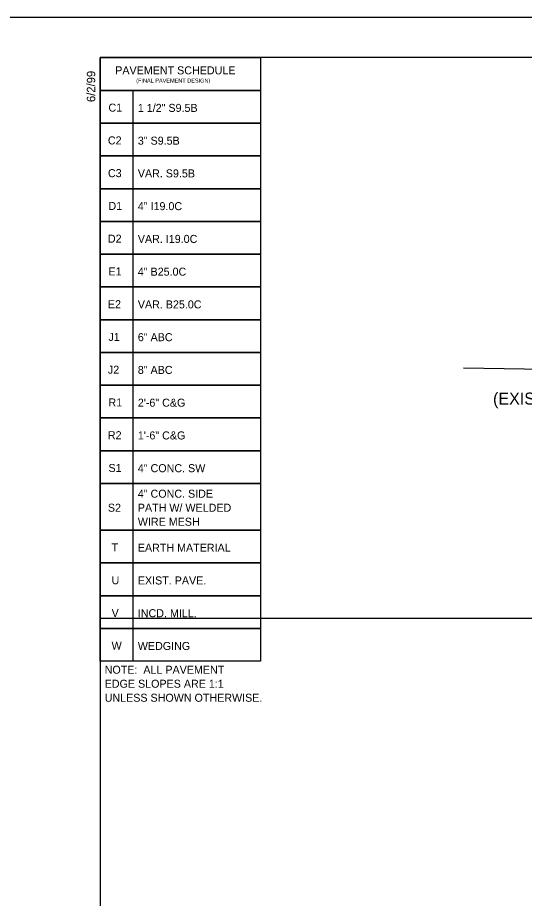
# Model space of a CAD drawing. Extents: x 1487909 to 1489267, y 497866 to 499814.
# Drawn here: x 1488894.8 to 1488926.4, y 498162.1 to 498217.1 of the extents above; entities that cross this region are included whole.
import ezdxf

# ---------------------------------------------------------------- set-up
doc = ezdxf.new("R2010")
doc.units = 0
for name, color, linetype in [('Prop Pavement Schedule Description CELL', 7, 'Continuous'), ('Scratch_Level_1', 7, 'Continuous'), ('Sheet Plot Border Outside CELL', 7, 'Continuous'), ('Sheet Typical CELL', 7, 'Continuous'), ('Typical Hinge Slope Arterial CELL', 7, 'Continuous'), ('Typical Pavement Slope CELL', 7, 'Continuous')]:
    doc.layers.add(name, color=color, linetype=linetype)

msp = doc.modelspace()

# ---------------------------------------------------------------- linework, layer by layer
at = {"layer": 'Prop Pavement Schedule Description CELL'}
for points in [[(1488902.009, 498212.542), (1488899.964, 498212.542), (1488899.964, 498214.587), (1488909.964, 498214.587), (1488909.964, 498212.542), (1488902.009, 498212.542)], [(1488902.009, 498210.496), (1488899.964, 498210.496), (1488899.964, 498212.542), (1488909.964, 498212.542), (1488909.964, 498210.496), (1488902.009, 498210.496), (1488902.009, 498212.542)], [(1488902.009, 498208.451), (1488899.964, 498208.451), (1488899.964, 498210.496), (1488909.964, 498210.496), (1488909.964, 498208.451), (1488902.009, 498208.451), (1488902.009, 498210.496)], [(1488902.009, 498206.405), (1488899.964, 498206.405), (1488899.964, 498208.451), (1488909.964, 498208.451), (1488909.964, 498206.405), (1488902.009, 498206.405), (1488902.009, 498208.451)], [(1488902.009, 498204.36), (1488899.964, 498204.36), (1488899.964, 498206.405), (1488909.964, 498206.405), (1488909.964, 498204.36), (1488902.009, 498204.36), (1488902.009, 498206.405)], [(1488902.009, 498202.314), (1488899.964, 498202.314), (1488899.964, 498204.36), (1488909.964, 498204.36), (1488909.964, 498202.314), (1488902.009, 498202.314), (1488902.009, 498204.36)], [(1488902.009, 498200.269), (1488899.964, 498200.269), (1488899.964, 498202.314), (1488909.964, 498202.314), (1488909.964, 498200.269), (1488902.009, 498200.269), (1488902.009, 498202.314)], [(1488902.009, 498198.224), (1488899.964, 498198.224), (1488899.964, 498200.269), (1488909.964, 498200.269), (1488909.964, 498198.224), (1488902.009, 498198.224), (1488902.009, 498200.269)], [(1488902.009, 498196.178), (1488899.964, 498196.178), (1488899.964, 498198.224), (1488909.964, 498198.224), (1488909.964, 498196.178), (1488902.009, 498196.178), (1488902.009, 498198.224)], [(1488902.009, 498194.133), (1488899.964, 498194.133), (1488899.964, 498196.178), (1488909.964, 498196.178), (1488909.964, 498194.133), (1488902.009, 498194.133), (1488902.009, 498196.178)], [(1488902.009, 498192.087), (1488899.964, 498192.087), (1488899.964, 498194.133), (1488909.964, 498194.133), (1488909.964, 498192.087), (1488902.009, 498192.087), (1488902.009, 498194.133)], [(1488902.009, 498190.042), (1488899.964, 498190.042), (1488899.964, 498192.087), (1488909.964, 498192.087), (1488909.964, 498190.042), (1488902.009, 498190.042), (1488902.009, 498192.087)], [(1488902.009, 498187.997), (1488899.964, 498187.997), (1488899.964, 498190.042), (1488909.964, 498190.042), (1488909.964, 498187.997), (1488902.009, 498187.997), (1488902.009, 498190.042)], [(1488902.009, 498185.076), (1488899.964, 498185.076), (1488899.964, 498187.997), (1488909.964, 498187.997), (1488909.964, 498185.076), (1488902.009, 498185.076), (1488902.009, 498187.997)], [(1488902.009, 498183.031), (1488899.964, 498183.031), (1488899.964, 498185.076), (1488909.964, 498185.076), (1488909.964, 498183.031), (1488902.009, 498183.031), (1488902.009, 498185.076)], [(1488902.009, 498180.986), (1488899.964, 498180.986), (1488899.964, 498183.031), (1488909.964, 498183.031), (1488909.964, 498180.986), (1488902.009, 498180.986), (1488902.009, 498183.031)], [(1488902.009, 498178.94), (1488899.964, 498178.94), (1488899.964, 498180.986), (1488909.964, 498180.986), (1488909.964, 498178.94), (1488902.009, 498178.94), (1488902.009, 498180.986)], [(1488902.009, 498176.895), (1488899.964, 498176.895), (1488899.964, 498178.94), (1488909.964, 498178.94), (1488909.964, 498176.895), (1488902.009, 498176.895), (1488902.009, 498178.94)]]:
    msp.add_lwpolyline(points, dxfattribs=at)
at = {"layer": 'Scratch_Level_1'}
msp.add_line((1488899.964, 498179.587), (1489049.964, 498179.587), dxfattribs=at)
at = {"layer": 'Sheet Plot Border Outside CELL'}
msp.add_lwpolyline([(1489051.664, 498217.087), (1488883.264, 498217.087), (1488883.264, 498107.087), (1489051.664, 498107.087)], close=True, dxfattribs=at)
at = {"layer": 'Sheet Typical CELL'}
msp.add_lwpolyline([(1489049.964, 498214.587), (1488899.964, 498214.587), (1488899.964, 498109.587), (1489049.964, 498109.587)], close=True, dxfattribs=at)
at = {"layer": 'Typical Pavement Slope CELL'}
msp.add_line((1488942.964, 498194.8), (1488922.63, 498195.206), dxfattribs=at)

# ---------------------------------------------------------------- texts
at = {"layer": 'Prop Pavement Schedule Description CELL'}
for s, height, p in [('PAVEMENT SCHEDULE', 0.5, (1488900.896, 498213.543)), ('(FINAL PAVEMENT DESIGN)', 0.25, (1488902.206, 498213.031)), ('C1', 0.5, (1488900.473, 498211.215)), (' 1 1/2" S9.5B', 0.5, (1488902.121, 498211.2)), ('C2', 0.5, (1488900.438, 498209.169)), (' 3" S9.5B', 0.5, (1488902.121, 498209.155)), ('C3', 0.5, (1488900.441, 498207.124)), (' VAR. S9.5B', 0.5, (1488902.121, 498207.109)), ('D1', 0.5, (1488900.473, 498205.078)), (' 4" I19.0C', 0.5, (1488902.121, 498205.064)), ('D2', 0.5, (1488900.438, 498203.033)), (' VAR. I19.0C', 0.5, (1488902.121, 498203.018)), ('E1', 0.5, (1488900.473, 498200.987)), (' 4" B25.0C', 0.5, (1488902.121, 498200.973)), ('E2', 0.5, (1488900.438, 498198.942)), (' VAR. B25.0C', 0.5, (1488902.121, 498198.928)), ('J1', 0.5, (1488900.473, 498196.897)), (' 6" ABC', 0.5, (1488902.121, 498196.882)), ('J2', 0.5, (1488900.438, 498194.851)), (' 8" ABC', 0.5, (1488902.121, 498194.837)), ('R1', 0.5, (1488900.473, 498192.806)), (' 2\'-6" C&G', 0.5, (1488902.121, 498192.791)), ('R2', 0.5, (1488900.438, 498190.76)), (' 1\'-6" C&G', 0.5, (1488902.121, 498190.746)), ('S1', 0.5, (1488900.473, 498188.715)), (' 4" CONC. SW', 0.5, (1488902.121, 498188.701)), (' 4" CONC. SIDE', 0.5, (1488902.121, 498187.107)), ('S2', 0.5, (1488900.438, 498186.232)), (' PATH W/ WELDED', 0.5, (1488902.121, 498186.232)), (' WIRE MESH', 0.5, (1488902.121, 498185.357)), ('T', 0.5, (1488900.669, 498183.749)), (' EARTH MATERIAL', 0.5, (1488902.121, 498183.735)), ('U', 0.5, (1488900.669, 498181.704)), (' EXIST. PAVE.', 0.5, (1488902.121, 498181.69)), ('V', 0.5, (1488900.671, 498179.659)), (' INCD. MILL.', 0.5, (1488902.121, 498179.644)), ('W', 0.5, (1488900.669, 498177.613)), (' WEDGING', 0.5, (1488902.121, 498177.599)), ('NOTE:  ALL PAVEMENT', 0.5, (1488900.238, 498176.116)), ('EDGE SLOPES ARE 1:1 ', 0.5, (1488900.238, 498175.241)), ('UNLESS SHOWN OTHERWISE.', 0.5, (1488900.238, 498174.366))]:
    msp.add_text(s, height=height, dxfattribs=at).set_placement(p)
at = {"layer": 'Sheet Typical CELL'}
msp.add_text('6/2/99', height=0.525, rotation=90, dxfattribs=at).set_placement((1488899.649, 498211.812))
at = {"layer": 'Typical Hinge Slope Arterial CELL'}
msp.add_text('(EXISTING RAILROAD GRADE)', height=0.75, dxfattribs=at).set_placement((1488924.48, 498192.921))

doc.saveas('drawing.dxf')
